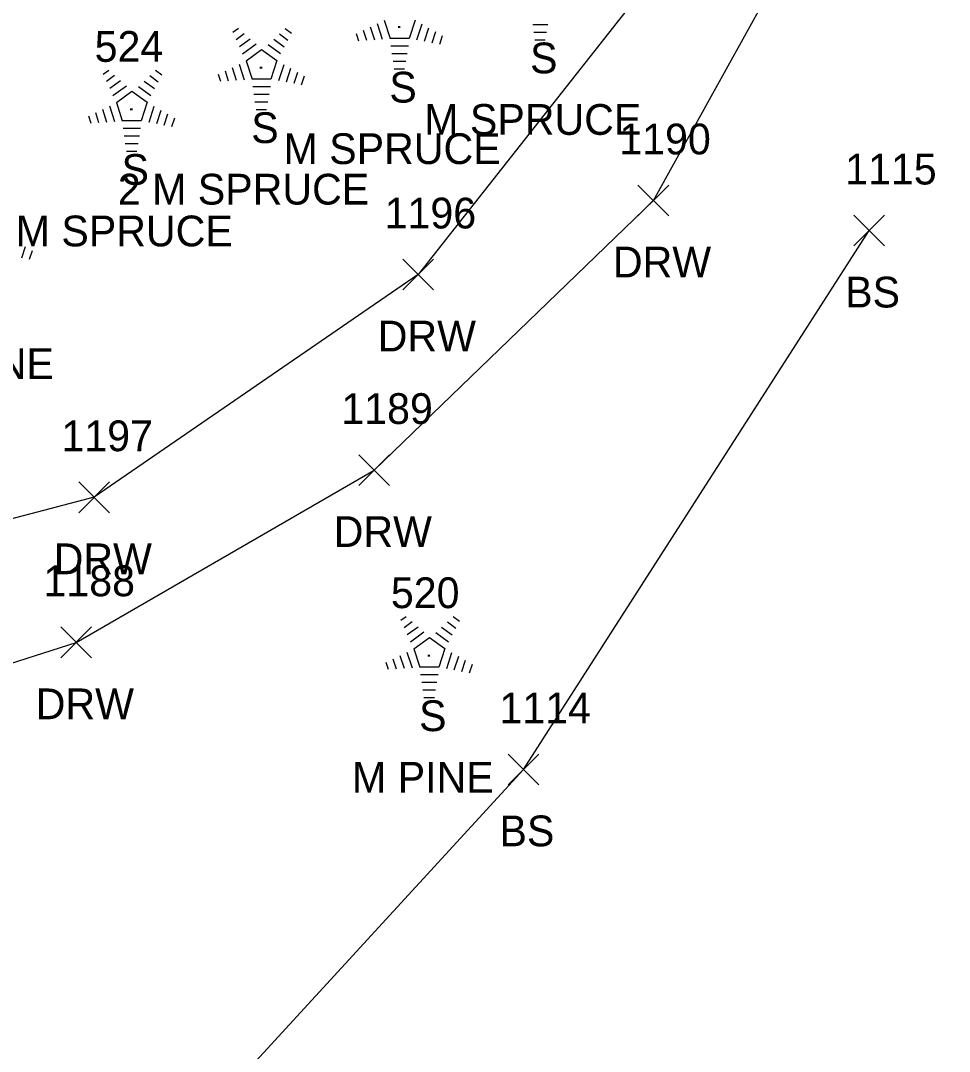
# Model space of a CAD drawing. Extents: x 1545627 to 1546562, y 571176 to 576667.
# Drawn here: x 1546240.9 to 1546301.3, y 571824 to 571891 of the extents above; entities that cross this region are included whole.
import ezdxf

# ---------------------------------------------------------------- set-up
doc = ezdxf.new("R2010")
doc.units = 0
for name, color, linetype in [('L_A', 7, 'Continuous'), ('L_C', 7, 'Continuous'), ('L_I', 7, 'Continuous'), ('L_TIC', 7, 'Continuous'), ('LELB', 7, 'Continuous'), ('LTC', 7, 'Continuous'), ('R_A', 7, 'Continuous'), ('R_I', 7, 'Continuous'), ('R_TIC', 7, 'Continuous'), ('RDW', 7, 'Continuous')]:
    doc.layers.add(name, color=color, linetype=linetype)

msp = doc.modelspace()

# ---------------------------------------------------------------- linework, layer by layer
at = {"layer": 'L_TIC'}
for points in [[(1546295.057, 571876.376), (1546297.057, 571878.376)], [(1546297.057, 571876.376), (1546295.057, 571878.376)], [(1546272.581, 571841.334), (1546274.581, 571843.334)], [(1546274.581, 571841.334), (1546272.581, 571843.334)]]:
    msp.add_lwpolyline(points, dxfattribs=at)
at = {"layer": 'LELB'}
msp.add_lwpolyline([(1546291.362, 571726.246), (1546280.537, 571754.219), (1546266.568, 571778.999), (1546255.287, 571800.294), (1546248.229, 571814.682), (1546273.581, 571842.334), (1546296.057, 571877.376)], dxfattribs=at)
at = {"layer": 'LTC'}
for p, q in [((1546263.615, 571890.626), (1546263.886, 571889.79)), ((1546264.07, 571890.842), (1546264.401, 571889.823)), ((1546264.525, 571891.061), (1546264.912, 571889.868)), ((1546266.534, 571891.071), (1546266.142, 571889.868)), ((1546266.971, 571890.8), (1546266.633, 571889.76)), ((1546275.169, 571890.768), (1546274.181, 571890.768)), ((1546254.692, 571890.278), (1546255.046, 571890.536)), ((1546254.901, 571889.813), (1546255.43, 571890.197)), ((1546257.719, 571890.17), (1546258.268, 571889.771)), ((1546258.09, 571890.519), (1546258.509, 571890.214)), ((1546262.704, 571890.192), (1546262.856, 571889.724)), ((1546263.159, 571890.409), (1546263.371, 571889.757)), ((1546267.416, 571890.549), (1546267.128, 571889.665)), ((1546267.86, 571890.299), (1546267.623, 571889.57)), ((1546268.304, 571890.049), (1546268.118, 571889.475)), ((1546275.085, 571890.268), (1546274.254, 571890.268)), ((1546255.111, 571889.347), (1546255.815, 571889.858)), ((1546255.32, 571888.881), (1546256.199, 571889.519)), ((1546256.977, 571889.474), (1546257.786, 571888.885)), ((1546257.348, 571889.822), (1546258.027, 571889.328)), ((1546266.142, 571889.868), (1546264.912, 571889.868)), ((1546266.104, 571889.368), (1546264.959, 571889.368)), ((1546275.001, 571889.768), (1546274.326, 571889.768)), ((1546255.545, 571888.426), (1546256.557, 571889.161)), ((1546256.557, 571889.161), (1546257.554, 571888.436)), ((1546266.02, 571888.868), (1546265.032, 571888.868)), ((1546254.635, 571887.991), (1546254.906, 571887.155)), ((1546255.09, 571888.207), (1546255.421, 571887.188)), ((1546255.545, 571888.426), (1546255.932, 571887.233)), ((1546257.554, 571888.436), (1546257.162, 571887.233)), ((1546257.991, 571888.165), (1546257.653, 571887.125)), ((1546258.436, 571887.915), (1546258.148, 571887.03)), ((1546265.937, 571888.368), (1546265.105, 571888.368)), ((1546246.258, 571887.561), (1546246.612, 571887.819)), ((1546246.467, 571887.096), (1546246.996, 571887.48)), ((1546249.285, 571887.453), (1546249.834, 571887.054)), ((1546249.656, 571887.802), (1546250.075, 571887.497)), ((1546253.724, 571887.557), (1546253.876, 571887.09)), ((1546254.18, 571887.774), (1546254.391, 571887.122)), ((1546258.88, 571887.665), (1546258.643, 571886.935)), ((1546259.325, 571887.414), (1546259.138, 571886.84)), ((1546265.853, 571887.868), (1546265.178, 571887.868)), ((1546246.677, 571886.63), (1546247.381, 571887.141)), ((1546246.886, 571886.164), (1546247.765, 571886.802)), ((1546248.543, 571886.757), (1546249.352, 571886.168)), ((1546248.914, 571887.105), (1546249.593, 571886.611)), ((1546257.162, 571887.233), (1546255.932, 571887.233)), ((1546257.124, 571886.733), (1546255.98, 571886.733)), ((1546247.111, 571885.709), (1546248.123, 571886.444)), ((1546248.123, 571886.444), (1546249.12, 571885.719)), ((1546257.04, 571886.233), (1546256.052, 571886.233)), ((1546246.201, 571885.274), (1546246.472, 571884.438)), ((1546246.656, 571885.49), (1546246.987, 571884.471)), ((1546247.111, 571885.709), (1546247.498, 571884.516)), ((1546249.12, 571885.719), (1546248.729, 571884.516)), ((1546249.557, 571885.448), (1546249.219, 571884.408)), ((1546256.957, 571885.733), (1546256.125, 571885.733)), ((1546256.873, 571885.233), (1546256.198, 571885.233)), ((1546245.29, 571884.84), (1546245.442, 571884.373)), ((1546245.746, 571885.057), (1546245.957, 571884.405)), ((1546250.002, 571885.198), (1546249.714, 571884.313)), ((1546250.446, 571884.948), (1546250.209, 571884.218)), ((1546250.891, 571884.697), (1546250.704, 571884.123)), ((1546248.729, 571884.516), (1546247.498, 571884.516)), ((1546248.69, 571884.016), (1546247.546, 571884.016)), ((1546248.606, 571883.516), (1546247.618, 571883.516)), ((1546248.523, 571883.016), (1546247.691, 571883.016)), ((1546248.439, 571882.516), (1546247.764, 571882.516)), ((1546241.191, 571876.315), (1546240.954, 571875.585)), ((1546241.635, 571876.064), (1546241.448, 571875.49)), ((1546265.605, 571852.032), (1546265.959, 571852.289)), ((1546265.814, 571851.566), (1546266.344, 571851.95)), ((1546268.632, 571851.924), (1546269.182, 571851.524)), ((1546269.003, 571852.272), (1546269.422, 571851.967)), ((1546266.024, 571851.1), (1546266.728, 571851.612)), ((1546266.234, 571850.634), (1546267.112, 571851.272)), ((1546267.89, 571851.227), (1546268.699, 571850.638)), ((1546268.261, 571851.575), (1546268.94, 571851.082)), ((1546266.458, 571850.179), (1546267.47, 571850.914)), ((1546267.47, 571850.914), (1546268.467, 571850.189)), ((1546265.548, 571849.744), (1546265.819, 571848.909)), ((1546266.004, 571849.96), (1546266.334, 571848.941)), ((1546266.458, 571850.179), (1546266.845, 571848.986)), ((1546268.467, 571850.189), (1546268.076, 571848.986)), ((1546268.904, 571849.918), (1546268.567, 571848.879)), ((1546264.637, 571849.311), (1546264.789, 571848.843)), ((1546265.093, 571849.527), (1546265.304, 571848.876)), ((1546269.349, 571849.668), (1546269.062, 571848.783)), ((1546269.794, 571849.418), (1546269.557, 571848.688)), ((1546270.238, 571849.167), (1546270.051, 571848.593)), ((1546268.076, 571848.986), (1546266.845, 571848.986)), ((1546268.037, 571848.486), (1546266.893, 571848.486)), ((1546267.954, 571847.986), (1546266.965, 571847.986)), ((1546267.87, 571847.486), (1546267.038, 571847.486)), ((1546267.786, 571846.986), (1546267.111, 571846.986))]:
    msp.add_line(p, q, dxfattribs=at)
at = {"layer": 'R_TIC'}
for points in [[(1546281.026, 571878.334), (1546283.026, 571880.334)], [(1546283.026, 571878.334), (1546281.026, 571880.334)], [(1546265.736, 571873.517), (1546267.736, 571875.517)], [(1546267.736, 571873.517), (1546265.736, 571875.517)], [(1546262.872, 571860.801), (1546264.872, 571862.801)], [(1546264.872, 571860.801), (1546262.872, 571862.801)], [(1546244.666, 571859.03), (1546246.666, 571861.03)], [(1546246.666, 571859.03), (1546244.666, 571861.03)], [(1546243.499, 571849.597), (1546245.499, 571851.597)], [(1546245.499, 571849.597), (1546243.499, 571851.597)]]:
    msp.add_lwpolyline(points, dxfattribs=at)
at = {"layer": 'RDW'}
for points in [[(1546294.555, 571953.756), (1546290.538, 571919.039), (1546284.539, 571897.111), (1546266.736, 571874.517), (1546245.666, 571860.03), (1546228.586, 571855.541), (1546223.567, 571853.749), (1546218.613, 571853), (1546210.358, 571854.991), (1546208.219, 571856.105), (1546205.182, 571857.755)], [(1546213.044, 571834.88), (1546214.931, 571836.379), (1546217.305, 571838.705), (1546220.817, 571841.735), (1546225.642, 571844.556), (1546244.499, 571850.597), (1546263.872, 571861.801), (1546282.026, 571879.334), (1546296.805, 571905.979), (1546303.893, 571951.142)]]:
    msp.add_lwpolyline(points, dxfattribs=at)

# ---------------------------------------------------------------- texts
at = {"layer": 'L_A'}
for s, p in [('S', (1546274.011, 571887.605)), ('S', (1546264.862, 571885.705)), ('S', (1546255.882, 571883.07)), ('S', (1546247.448, 571880.353)), ('BS', (1546294.498, 571872.376)), ('S', (1546266.796, 571844.823)), ('BS', (1546272.022, 571837.334))]:
    msp.add_text(s, height=2, dxfattribs=at).set_placement(p)
at = {"layer": 'L_C'}
for s, p in [('M SPRUCE', (1546267.129, 571883.605)), ('M SPRUCE', (1546257.98, 571881.705)), ('2 M SPRUCE', (1546247.205, 571879.07)), ('M SPRUCE', (1546240.566, 571876.353)), ('M PINE', (1546233.831, 571867.72)), ('M PINE', (1546262.433, 571840.823))]:
    msp.add_text(s, height=2, dxfattribs=at).set_placement(p)
at = {"layer": 'L_I'}
for s, p in [('524', (1546245.7, 571888.353)), ('1115', (1546294.498, 571880.376)), ('520', (1546264.961, 571852.823)), ('1114', (1546272.022, 571845.334))]:
    msp.add_text(s, height=2, dxfattribs=at).set_placement(p)
at = {"layer": 'LTC'}
for p in [(1546265.419, 571890.809), (1546256.439, 571888.174), (1546248.005, 571885.457), (1546267.352, 571849.927)]:
    msp.add_text('.', height=1.037, rotation=270, dxfattribs=at).set_placement(p)
at = {"layer": 'R_A'}
for p in [(1546279.396, 571874.334), (1546264.106, 571869.517), (1546261.242, 571856.801), (1546243.036, 571855.03), (1546241.869, 571845.597)]:
    msp.add_text('DRW', height=2, dxfattribs=at).set_placement(p)
at = {"layer": 'R_I'}
for s, p in [('1190', (1546279.813, 571882.334)), ('1196', (1546264.555, 571877.517)), ('1189', (1546261.738, 571864.801)), ('1197', (1546243.54, 571863.03)), ('1188', (1546242.373, 571853.597))]:
    msp.add_text(s, height=2, dxfattribs=at).set_placement(p)

doc.saveas('drawing.dxf')
